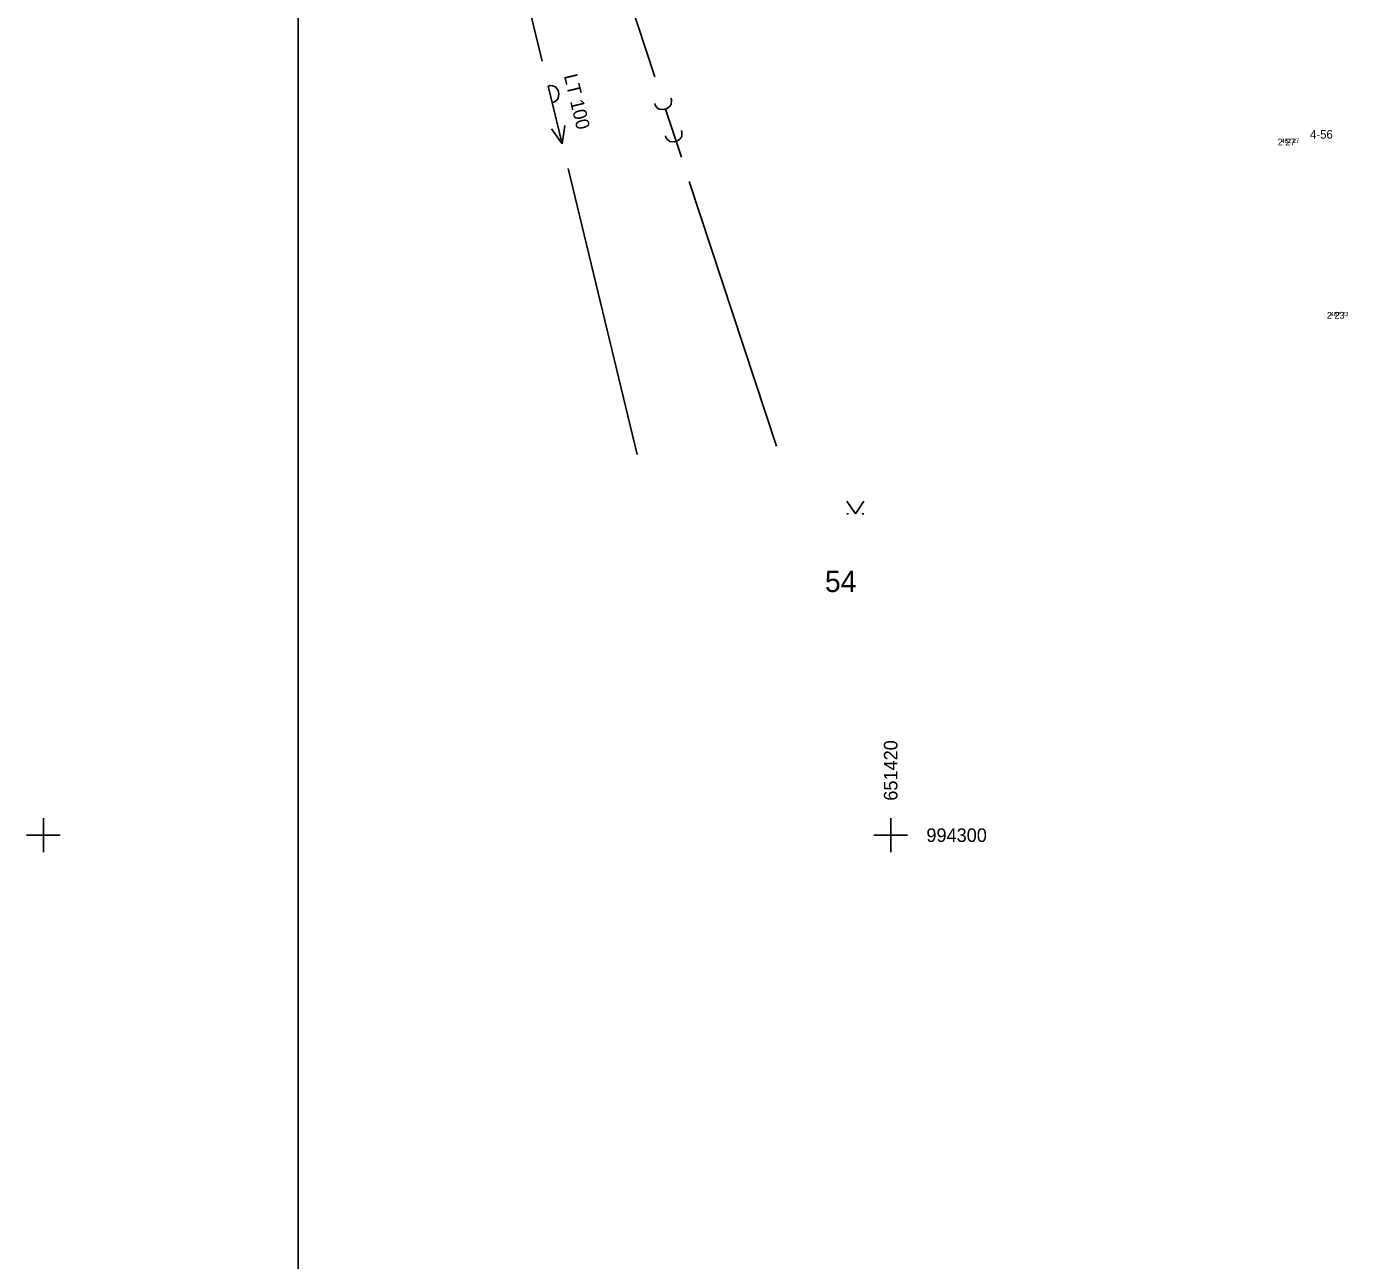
# Model space of a CAD drawing. Extents: x -651478 to -651308, y -994378 to -994071.
# Drawn here: x -651440.4 to -651409.22, y -994310.04 to -994280.91 of the extents above; entities that cross this region are included whole.
import ezdxf

# ---------------------------------------------------------------- set-up
doc = ezdxf.new("R2010")
doc.units = 0
for name, color, linetype in [('18_TECKY_BODU', 7, 'Continuous'), ('19_CISLA_BODU', 7, 'Continuous'), ('20_REDUKOVANE_VYSKY_BODU', 7, 'Continuous'), ('34_KANAL-VEDENI', 7, 'Continuous'), ('38_VODA-VEDENI', 7, 'Continuous'), ('61_UPLNE_VYSKY_BODU', 7, 'Continuous'), ('_KM', 7, 'Continuous'), ('rezy', 7, 'Continuous'), ('ROZP', 7, 'Continuous')]:
    doc.layers.add(name, color=color, linetype=linetype)

# ---------------------------------------------------------------- blocks, each defined once
blk = doc.blocks.new('POINT_DISPLAY')
blk.add_line((0, 0), (0, 0))
blk = doc.blocks.new('Z3140')
for p, q in [((-0.2, 0.3), (0, 0)), ((-0.2, 0), (-0.16, 0)), ((0, 0), (0.2, 0.3)), ((0.16, 0), (0.2, 0))]:
    blk.add_line(p, q)
blk = doc.blocks.new('Z70')
for p, q in [((0, -0.4), (0, 0.4)), ((-0.4, 0), (0.4, 0))]:
    blk.add_line(p, q)
blk = doc.blocks.new('Z616')
for p, q in [((-0.68, 0.1), (-0.7, 0.04)), ((-0.7, 0.04), (-0.7, 0)), ((-0.7, 0), (0.7, 0)), ((-0.64, 0.16), (-0.68, 0.1)), ((-0.54, 0.2), (-0.64, 0.16)), ((-0.46, 0.2), (-0.54, 0.2)), ((-0.36, 0.16), (-0.46, 0.2)), ((-0.32, 0.1), (-0.36, 0.16)), ((-0.3, 0.04), (-0.32, 0.1)), ((-0.3, 0), (-0.3, 0.04)), ((0.3, 0.16), (0.7, 0)), ((0.7, 0), (0.3, -0.16))]:
    blk.add_line(p, q)
blk = doc.blocks.new('Z627')
for p, q in [((-0.7, 0.2), (-0.66, 0.2)), ((-0.66, 0.2), (-0.56, 0.16)), ((-0.56, 0.16), (-0.52, 0.1)), ((-0.52, 0.1), (-0.5, 0.04)), ((-0.5, 0.04), (-0.5, -0.04)), ((-0.5, 0), (0.7, 0)), ((0.1, 0.2), (0.14, 0.2)), ((0.14, 0.2), (0.24, 0.16)), ((0.24, 0.16), (0.28, 0.1)), ((0.28, 0.1), (0.3, 0.04)), ((0.3, 0.04), (0.3, -0.04)), ((-0.66, -0.2), (-0.7, -0.2)), ((-0.6, -0.18), (-0.66, -0.2)), ((-0.54, -0.14), (-0.6, -0.18)), ((-0.5, -0.04), (-0.54, -0.14)), ((0.14, -0.2), (0.1, -0.2)), ((0.2, -0.18), (0.14, -0.2)), ((0.26, -0.14), (0.2, -0.18)), ((0.3, -0.04), (0.26, -0.14))]:
    blk.add_line(p, q)

msp = doc.modelspace()

# ---------------------------------------------------------------- linework, layer by layer
at = {"layer": '34_KANAL-VEDENI'}
for p, q in [((-651429.357, -994270.618), (-651425.567, -994282.102)), ((-651424.753, -994284.571), (-651422.691, -994290.818))]:
    msp.add_line(p, q, dxfattribs=at)
at = {"layer": '38_VODA-VEDENI'}
for p, q in [((-651430.599, -994271.9), (-651428.225, -994281.735)), ((-651427.615, -994284.262), (-651425.985, -994291.015))]:
    msp.add_line(p, q, dxfattribs=at)
at = {"layer": 'rezy'}
msp.add_line((-651433.983, -994242.69), (-651433.983, -994326.69), dxfattribs=at)

# ---------------------------------------------------------------- block references
at = {"layer": '18_TECKY_BODU'}
for p in [(-651410.5, -994283.56), (-651409.34, -994287.65)]:
    msp.add_blockref('POINT_DISPLAY', p, dxfattribs=at)
at = {"layer": '34_KANAL-VEDENI', "rotation": -71.73649999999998}
msp.add_blockref('Z627', (-651425.16, -994283.336), dxfattribs=at)
at = {"layer": '38_VODA-VEDENI', "rotation": -76.4296}
msp.add_blockref('Z616', (-651427.92, -994282.999), dxfattribs=at)
at = {"layer": '_KM'}
msp.add_blockref('Z3140', (-651420.834, -994292.418), dxfattribs=at)
at = {"layer": 'ROZP'}
for p in [(-651440, -994300), (-651420, -994300)]:
    msp.add_blockref('Z70', p, dxfattribs=at)

# ---------------------------------------------------------------- texts
at = {"layer": '19_CISLA_BODU'}
msp.add_text('4-56', height=0.2, dxfattribs=at).set_placement((-651410.1, -994283.56))
at = {"layer": '20_REDUKOVANE_VYSKY_BODU'}
for s, p in [(' 2 27', (-651410.923, -994283.72)), (' 2 23', (-651409.763, -994287.81))]:
    msp.add_text(s, height=0.16, dxfattribs=at).set_placement(p)
at = {"layer": '38_VODA-VEDENI'}
msp.add_text('LT 100', height=0.32, rotation=283.5704, dxfattribs=at).set_placement((-651427.715, -994282.076))
at = {"layer": '61_UPLNE_VYSKY_BODU'}
for s, p in [('482 27 ', (-651410.779, -994283.66)), ('482 23 ', (-651409.618, -994287.75))]:
    msp.add_text(s, height=0.1, dxfattribs=at).set_placement(p)
at = {"layer": '_KM'}
msp.add_text('54', height=0.5, dxfattribs=at).set_placement((-651421.552, -994294.261))
at = {"layer": 'ROZP'}
msp.add_text('651420', height=0.32, rotation=90, dxfattribs=at).set_placement((-651419.84, -994299.187))
msp.add_text('994300', height=0.32, dxfattribs=at).set_placement((-651419.157, -994300.16))

doc.saveas('drawing.dxf')
